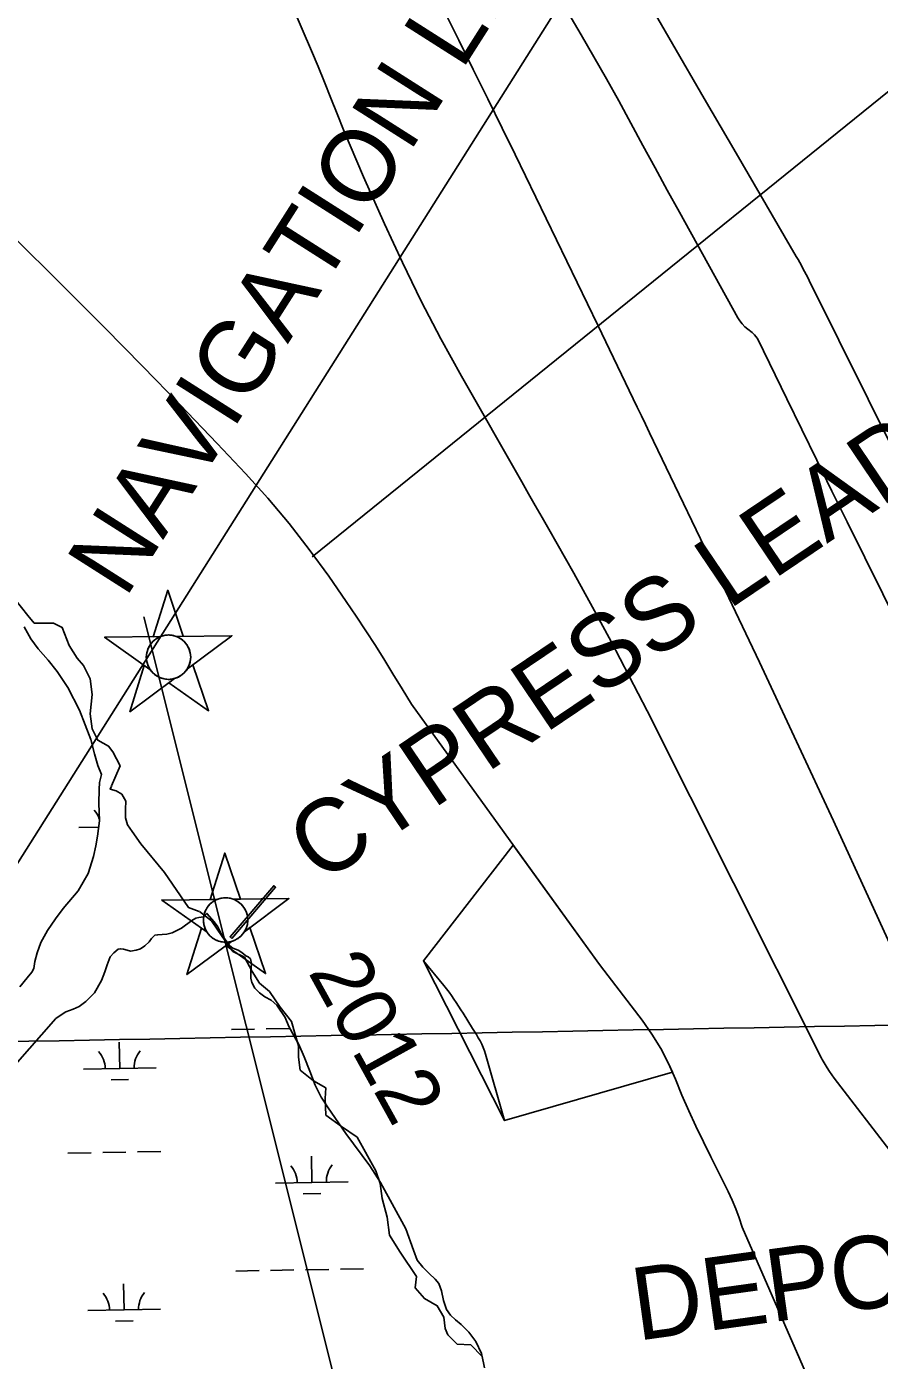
# Model space of a CAD drawing. Extents: x 3925854 to 3964121, y 224593 to 250589.
# Drawn here: x 3946796 to 3947969, y 235951 to 237787 of the extents above; entities that cross this region are included whole.
import ezdxf

# ---------------------------------------------------------------- set-up
doc = ezdxf.new("R2010")
doc.units = 0
for name, color, linetype in [('V-CHAN-DOCK', 7, 'Continuous'), ('V-CHAN-NAID', 7, 'Continuous'), ('V-GRID-MAJR', 7, 'Continuous'), ('V-RIVR-EDGE', 7, 'Continuous'), ('V-RIVR-IDEN', 7, 'Continuous'), ('V-RIVR-RANG', 7, 'Continuous'), ('V-TOPO-DPTH', 7, 'Continuous'), ('V-TOPO-MINR', 7, 'Continuous'), ('V-TOPO-SHOR', 7, 'Continuous'), ('V-UTIL-LINE', 7, 'Continuous'), ('V-WETL-SWMP', 7, 'Continuous')]:
    doc.layers.add(name, color=color, linetype=linetype)

msp = doc.modelspace()

# ---------------------------------------------------------------- linework, layer by layer
at = {"layer": 'V-CHAN-DOCK'}
msp.add_lwpolyline([(3947078.594, 236531.524), (3947138.764, 236602.031), (3947136.27, 236604.161), (3947076.098, 236533.654), (3947078.594, 236531.524)], dxfattribs=at)
at = {"layer": 'V-CHAN-NAID'}
for points in [[(3946980.066, 236947.098), (3946970.48, 236946.979), (3946990.365, 237010.862), (3947011.828, 236947.491), (3947002.241, 236947.373), (3947000.653, 236947.92), (3946998.547, 236948.499), (3946996.498, 236948.91), (3946994.457, 236949.178), (3946993.288, 236949.269), (3946991.752, 236949.321), (3946990.031, 236949.285), (3946988.662, 236949.188), (3946986.76, 236948.95), (3946985.399, 236948.705), (3946983.623, 236948.286), (3946982.101, 236947.836), (3946981.076, 236947.485)], [(3946980.066, 236947.098), (3946903.579, 236946.15), (3946966.017, 236901.958), (3946964.867, 236903.845), (3946964.025, 236905.457), (3946963.162, 236907.409), (3946962.426, 236909.449), (3946962.036, 236910.764), (3946961.643, 236912.383), (3946961.371, 236913.823), (3946961.152, 236915.417), (3946961.009, 236917.151), (3946960.966, 236918.731), (3946961.033, 236920.807), (3946961.184, 236922.428), (3946961.533, 236924.638), (3946961.977, 236926.57), (3946962.543, 236928.469), (3946963.165, 236930.16), (3946963.861, 236931.762), (3946964.645, 236933.313), (3946965.672, 236935.07), (3946966.674, 236936.56), (3946967.649, 236937.848), (3946968.629, 236939.013), (3946969.911, 236940.376), (3946970.943, 236941.361), (3946972.633, 236942.791), (3946973.828, 236943.684), (3946975.493, 236944.787), (3946977.206, 236945.766), (3946978.638, 236946.478)], [(3947002.241, 236947.373), (3947078.729, 236948.319), (3947017.405, 236902.594), (3947018.287, 236904.101), (3947019.229, 236905.967), (3947019.913, 236907.565), (3947020.614, 236909.534), (3947021.124, 236911.329), (3947021.49, 236912.976), (3947021.812, 236914.993), (3947021.967, 236916.569), (3947022.048, 236918.777), (3947021.978, 236920.838), (3947021.747, 236923.054), (3947021.446, 236924.806), (3947020.912, 236927.028), (3947020.23, 236929.155), (3947019.442, 236931.122), (3947018.766, 236932.553), (3947017.722, 236934.449), (3947016.626, 236936.15), (3947015.38, 236937.828), (3947014.089, 236939.342), (3947012.79, 236940.683), (3947011.129, 236942.183), (3947009.359, 236943.56), (3947007.653, 236944.704), (3947005.744, 236945.799), (3947004.258, 236946.532)], [(3946999.629, 236889.34), (3946938.305, 236843.615), (3946958.19, 236907.497), (3946966.017, 236901.958), (3946966.67, 236901.007), (3946968.089, 236899.175), (3946969.33, 236897.783), (3946970.825, 236896.309), (3946972.238, 236895.085), (3946973.714, 236893.958), (3946975.136, 236892.998), (3946976.834, 236891.995), (3946978.565, 236891.118), (3946980.372, 236890.342), (3946981.828, 236889.814), (3946983.466, 236889.317), (3946985.703, 236888.796), (3946987.24, 236888.539), (3946989.27, 236888.322), (3946990.809, 236888.248), (3946992.67, 236888.262), (3946994.357, 236888.373), (3946996.063, 236888.582), (3946997.959, 236888.93)], [(3947017.405, 236902.594), (3947025.091, 236908.326), (3947046.553, 236844.955), (3946991.942, 236883.609), (3946999.629, 236889.34), (3947001.285, 236889.848), (3947002.886, 236890.439), (3947005.026, 236891.395), (3947006.743, 236892.313), (3947008.587, 236893.463), (3947010.302, 236894.709), (3947011.83, 236895.984), (3947013.094, 236897.176), (3947014.45, 236898.623), (3947015.626, 236900.048), (3947016.717, 236901.542)], [(3947058.587, 236585.209), (3947049.001, 236585.09), (3947068.886, 236648.973), (3947090.349, 236585.602), (3947080.762, 236585.484), (3947079.174, 236586.031), (3947077.068, 236586.61), (3947075.019, 236587.021), (3947072.978, 236587.289), (3947071.809, 236587.38), (3947070.273, 236587.432), (3947068.552, 236587.396), (3947067.183, 236587.299), (3947065.281, 236587.061), (3947063.92, 236586.816), (3947062.144, 236586.397), (3947060.622, 236585.947), (3947059.597, 236585.596)], [(3947058.587, 236585.209), (3946982.1, 236584.261), (3947044.538, 236540.069), (3947043.388, 236541.956), (3947042.546, 236543.568), (3947041.683, 236545.52), (3947040.947, 236547.56), (3947040.557, 236548.875), (3947040.164, 236550.494), (3947039.892, 236551.934), (3947039.673, 236553.528), (3947039.53, 236555.262), (3947039.487, 236556.842), (3947039.554, 236558.918), (3947039.705, 236560.539), (3947040.054, 236562.749), (3947040.498, 236564.681), (3947041.064, 236566.58), (3947041.686, 236568.271), (3947042.382, 236569.873), (3947043.166, 236571.424), (3947044.193, 236573.181), (3947045.195, 236574.671), (3947046.17, 236575.959), (3947047.15, 236577.124), (3947048.432, 236578.487), (3947049.464, 236579.472), (3947051.154, 236580.902), (3947052.349, 236581.795), (3947054.014, 236582.898), (3947055.727, 236583.877), (3947057.159, 236584.589)], [(3947080.762, 236585.484), (3947157.25, 236586.43), (3947095.926, 236540.705), (3947096.808, 236542.212), (3947097.75, 236544.078), (3947098.434, 236545.676), (3947099.135, 236547.645), (3947099.645, 236549.44), (3947100.011, 236551.087), (3947100.333, 236553.104), (3947100.488, 236554.68), (3947100.569, 236556.888), (3947100.499, 236558.949), (3947100.268, 236561.165), (3947099.967, 236562.917), (3947099.433, 236565.139), (3947098.751, 236567.266), (3947097.963, 236569.233), (3947097.287, 236570.664), (3947096.243, 236572.56), (3947095.147, 236574.261), (3947093.901, 236575.939), (3947092.61, 236577.453), (3947091.311, 236578.794), (3947089.65, 236580.294), (3947087.88, 236581.671), (3947086.174, 236582.815), (3947084.265, 236583.91), (3947082.779, 236584.643)], [(3947078.15, 236527.451), (3947016.826, 236481.726), (3947036.711, 236545.608), (3947044.538, 236540.069), (3947045.191, 236539.118), (3947046.61, 236537.286), (3947047.851, 236535.894), (3947049.346, 236534.42), (3947050.759, 236533.196), (3947052.235, 236532.069), (3947053.657, 236531.109), (3947055.355, 236530.106), (3947057.086, 236529.229), (3947058.893, 236528.453), (3947060.349, 236527.925), (3947061.987, 236527.428), (3947064.224, 236526.907), (3947065.761, 236526.65), (3947067.791, 236526.433), (3947069.33, 236526.359), (3947071.191, 236526.373), (3947072.878, 236526.484), (3947074.584, 236526.693), (3947076.48, 236527.041)], [(3947095.926, 236540.705), (3947103.612, 236546.437), (3947125.074, 236483.066), (3947070.463, 236521.72), (3947078.15, 236527.451), (3947079.806, 236527.959), (3947081.407, 236528.55), (3947083.547, 236529.506), (3947085.264, 236530.424), (3947087.108, 236531.574), (3947088.823, 236532.82), (3947090.351, 236534.095), (3947091.615, 236535.287), (3947092.971, 236536.734), (3947094.147, 236538.159), (3947095.238, 236539.653)]]:
    msp.add_lwpolyline(points, close=True, dxfattribs=at)
for centre in [(3946991.506, 236918.781), (3947070.027, 236556.892)]:
    msp.add_circle(centre, 30.541, dxfattribs=at)
at = {"layer": 'V-GRID-MAJR'}
msp.add_spline([(3930006.603, 236087.686), (3935327.129, 236182.494), (3940647.643, 236278.076), (3945968.142, 236374.431), (3951288.627, 236471.56), (3956609.098, 236569.464), (3961929.554, 236668.141), (3961929.555, 236668.141)], degree=3, dxfattribs=at)
at = {"layer": 'V-RIVR-EDGE'}
for points in [[(3946780.342, 236997.96), (3946798.034, 236976.336), (3946806.88, 236965.524), (3946833.418, 236965.524), (3946845.213, 236959.627), (3946855.042, 236935.055), (3946865.854, 236917.362), (3946874.7, 236907.534), (3946883.546, 236888.858), (3946886.495, 236867.235), (3946883.546, 236840.697), (3946886.495, 236820.056), (3946894.358, 236804.329), (3946909.101, 236796.466), (3946914.999, 236788.603), (3946924.828, 236768.945), (3946913.033, 236741.424)], [(3946913.197, 236741.127), (3946911.283, 236736.98), (3946919.577, 236734.747), (3946927.233, 236729.962), (3946932.656, 236720.392), (3946932.337, 236709.546), (3946932.337, 236697.423), (3946934.889, 236687.853), (3946941.588, 236678.921), (3946953.391, 236661.695), (3946985.93, 236622.139), (3947018.787, 236573.969), (3947033.461, 236568.546)], [(3947033.929, 236568.434), (3947050.638, 236555.657), (3947065.382, 236534.033), (3947073.245, 236523.221), (3947080.125, 236513.392), (3947095.852, 236505.529), (3947106.663, 236485.871), (3947116.492, 236470.145), (3947130.253, 236458.35), (3947144.996, 236436.726), (3947160.723, 236417.068), (3947165.637, 236399.376), (3947170.552, 236383.65), (3947170.552, 236367.924), (3947172.517, 236350.232), (3947191.192, 236335.488), (3947207.902, 236325.659), (3947206.919, 236310.916), (3947207.902, 236288.309), (3947229.525, 236272.583), (3947251.149, 236257.839), (3947276.704, 236211.643), (3947282.602, 236193.951), (3947285.55, 236173.31), (3947292.431, 236147.755), (3947295.379, 236123.183), (3947310.123, 236099.593), (3947332.729, 236066.175), (3947330.764, 236050.448), (3947343.541, 236035.705), (3947361.233, 236025.876), (3947370.079, 236010.15), (3947372.045, 235994.423), (3947375.977, 235985.577), (3947388.755, 235972.8), (3947407.43, 235971.817), (3947423.156, 235956.09), (3947426.105, 235940.364)]]:
    msp.add_lwpolyline(points, dxfattribs=at)
at = {"layer": 'V-RIVR-RANG'}
msp.add_lwpolyline([(3946957.437, 236974.182), (3947380.075, 235285.015)], dxfattribs=at)
at = {"layer": 'V-TOPO-DPTH'}
msp.add_line((3947342.19, 236500.66), (3947453.89, 236280.69), dxfattribs=at)
for points in [[(3947403.666, 238040.429), (3947559.317, 237775.587), (3947576.826, 237745.398), (3947594.099, 237715.077), (3947611.02, 237684.558), (3947627.707, 237653.906), (3947644.275, 237623.188), (3947660.92, 237592.511), (3947677.68, 237561.897), (3947694.517, 237531.324), (3947774.824, 237386.155), (3947777.644, 237381.72), (3947780.785, 237377.559), (3947784.408, 237373.809), (3947788.351, 237370.334), (3947794.355, 237365.661), (3947797.736, 237362.677), (3947799.756, 237360.455), (3947801.441, 237357.994), (3947802.157, 237356.676), (3947842.097, 237274.575), (3947862.771, 237232.19), (3947883.504, 237189.833), (3947904.325, 237147.521), (3947925.205, 237105.237), (3948293.17, 236362.03)], [(3947988.605, 236233.372), (3947907.395, 236339.145), (3947904.009, 236343.741), (3947900.751, 236348.422), (3947897.681, 236353.23), (3947894.739, 236358.122), (3947890.826, 236364.932), (3947889.948, 236366.49), (3947889.089, 236368.057), (3947887.441, 236371.23), (3947649.862, 236845.126), (3947625.477, 236892.855), (3947600.611, 236940.328), (3947575.026, 236987.417), (3947548.96, 237034.25), (3947514.646, 237094.812), (3947505.37, 237111.167), (3947496.085, 237127.518), (3947486.787, 237143.861), (3947477.479, 237160.199), (3947394.556, 237305.613), (3947366.204, 237357.125), (3947338.91, 237409.171), (3947313.202, 237462.018), (3947288.551, 237515.4), (3947259.91, 237579.971), (3947250.516, 237601.528), (3947241.312, 237623.164), (3947232.39, 237644.919), (3947223.658, 237666.752), (3947214.974, 237688.607), (3947206.166, 237710.41), (3947197.171, 237732.138), (3947188.051, 237753.814), (3947161.353, 237816.515)], [(3947988.605, 236233.372), (3947907.395, 236339.145), (3947904.009, 236343.741), (3947900.751, 236348.422), (3947897.681, 236353.23), (3947894.739, 236358.122), (3947890.826, 236364.932), (3947889.948, 236366.49), (3947889.089, 236368.057), (3947887.441, 236371.23), (3947649.862, 236845.126), (3947625.477, 236892.855), (3947600.611, 236940.328), (3947575.026, 236987.417), (3947548.96, 237034.25), (3947514.646, 237094.812), (3947505.37, 237111.167), (3947496.085, 237127.518), (3947486.787, 237143.861), (3947477.479, 237160.199), (3947394.556, 237305.613), (3947366.204, 237357.125), (3947338.91, 237409.171), (3947313.202, 237462.018), (3947288.551, 237515.4), (3947259.91, 237579.971), (3947250.516, 237601.528), (3947241.312, 237623.164), (3947232.39, 237644.919), (3947223.658, 237666.752), (3947214.974, 237688.607), (3947206.166, 237710.41), (3947197.171, 237732.138), (3947188.051, 237753.814), (3947161.353, 237816.515)], [(3946688.902, 237586.154), (3946851.734, 237424.59), (3946904.003, 237372.225), (3946955.931, 237319.526), (3947007.347, 237266.328), (3947058.422, 237212.798), (3947097.489, 237171.455), (3947127.966, 237137.69), (3947157.368, 237103.055), (3947185.16, 237067.114), (3947211.878, 237030.303), (3947236.122, 236995.245), (3947249.749, 236975.203), (3947263.164, 236955.022), (3947276.26, 236934.633), (3947289.144, 236914.105), (3947300.337, 236895.955), (3947313.126, 236875.066), (3947325.822, 236854.122), (3947580.686, 236500.586), (3947585.905, 236494.019), (3947643.112, 236419.08), (3947656.559, 236399.848), (3947668.875, 236379.978), (3947679.492, 236359.151), (3947688.977, 236337.687), (3947697.891, 236315.865), (3947707.192, 236294.217), (3947717.076, 236272.828), (3947727.347, 236251.612), (3947737.792, 236230.76), (3947743.726, 236218.888), (3947749.646, 236207.009), (3947755.545, 236195.12), (3947761.431, 236183.224), (3947767.008, 236171.204), (3947772.191, 236159.028), (3947776.783, 236146.616), (3947780.98, 236134.048), (3948177.669, 235225.371)], [(3947684.725, 236347.309), (3947453.89, 236280.69), (3947427.726, 236372.119), (3947426.189, 236376.861), (3947424.438, 236381.514), (3947422.369, 236386.035), (3947420.087, 236390.466), (3947417.612, 236394.813), (3947415.097, 236399.134), (3947412.519, 236403.42), (3947409.901, 236407.681), (3947396.922, 236428.463), (3947393.801, 236433.412), (3947390.651, 236438.341), (3947387.457, 236443.242), (3947384.233, 236448.124), (3947380.913, 236452.937), (3947377.495, 236457.677), (3947373.929, 236462.306), (3947370.264, 236466.862), (3947342.19, 236500.66), (3947465.713, 236660.072)], [(3947465.713, 236660.072), (3947580.686, 236500.586), (3947585.905, 236494.019), (3947643.112, 236419.08), (3947656.559, 236399.848), (3947668.875, 236379.978), (3947679.492, 236359.151), (3947684.725, 236347.309)], [(3947453.89, 236280.69), (3947427.726, 236372.119), (3947426.189, 236376.861), (3947424.438, 236381.514), (3947422.369, 236386.035), (3947420.087, 236390.466), (3947417.612, 236394.813), (3947415.097, 236399.134), (3947412.519, 236403.42), (3947409.901, 236407.681), (3947396.922, 236428.463), (3947393.801, 236433.412), (3947390.651, 236438.341), (3947387.457, 236443.242), (3947384.233, 236448.124), (3947380.913, 236452.937), (3947377.495, 236457.677), (3947373.929, 236462.306), (3947370.264, 236466.862), (3947342.19, 236500.66)]]:
    msp.add_lwpolyline(points, dxfattribs=at)
at = {"layer": 'V-TOPO-MINR'}
for points in [[(3948293.17, 236362.03), (3947925.205, 237105.237), (3947904.325, 237147.521), (3947883.504, 237189.833), (3947862.771, 237232.19), (3947842.097, 237274.575), (3947802.157, 237356.676), (3947801.441, 237357.994), (3947799.756, 237360.455), (3947797.736, 237362.677), (3947794.355, 237365.661), (3947788.351, 237370.334), (3947784.408, 237373.809), (3947780.785, 237377.559), (3947777.644, 237381.72), (3947774.824, 237386.155), (3947694.517, 237531.324), (3947677.68, 237561.897), (3947660.92, 237592.511), (3947644.275, 237623.188), (3947627.707, 237653.906), (3947611.02, 237684.558), (3947594.099, 237715.077), (3947576.826, 237745.398), (3947559.317, 237775.587), (3947403.666, 238040.429)], [(3948319.902, 236537.459), (3947873.071, 237437.367), (3947870.955, 237441.58), (3947868.813, 237445.78), (3947866.633, 237449.96), (3947864.426, 237454.127), (3947862.179, 237458.271), (3947859.902, 237462.399), (3947857.58, 237466.502), (3947855.23, 237470.589), (3947772.35, 237612.929), (3947728.568, 237688.191), (3947684.829, 237763.478), (3947641.152, 237838.801)], [(3947988.605, 236233.372), (3947907.395, 236339.145), (3947904.009, 236343.741), (3947900.751, 236348.422), (3947897.681, 236353.23), (3947894.739, 236358.122), (3947890.826, 236364.932), (3947889.948, 236366.49), (3947889.089, 236368.057), (3947887.441, 236371.23), (3947649.862, 236845.126), (3947625.477, 236892.855), (3947600.611, 236940.328), (3947575.026, 236987.417), (3947548.96, 237034.25), (3947514.646, 237094.812), (3947505.37, 237111.167), (3947496.085, 237127.518), (3947486.787, 237143.861), (3947477.479, 237160.199), (3947394.556, 237305.613), (3947366.204, 237357.125), (3947338.91, 237409.171), (3947313.202, 237462.018), (3947288.551, 237515.4), (3947259.91, 237579.971), (3947250.516, 237601.528), (3947241.312, 237623.164), (3947232.39, 237644.919), (3947223.658, 237666.752), (3947214.974, 237688.607), (3947206.166, 237710.41), (3947197.171, 237732.138), (3947188.051, 237753.814), (3947161.353, 237816.515)], [(3948042.865, 236394.853), (3947956.573, 236584.258), (3947906.347, 236693.656), (3947855.697, 236802.856), (3947804.41, 236911.758), (3947752.699, 237020.462), (3947658.97, 237216.024), (3947653.356, 237227.733), (3947647.741, 237239.441), (3947642.123, 237251.148), (3947636.503, 237262.855), (3947582.23, 237375.885), (3947553.913, 237434.694), (3947525.511, 237493.463), (3947496.982, 237552.17), (3947468.369, 237610.836), (3947450.682, 237647), (3947430.804, 237687.532), (3947410.869, 237728.035), (3947390.846, 237768.494), (3947370.764, 237808.925)], [(3948177.669, 235225.371), (3947780.98, 236134.048), (3947776.783, 236146.616), (3947772.191, 236159.028), (3947767.008, 236171.204), (3947761.431, 236183.224), (3947755.545, 236195.12), (3947749.646, 236207.009), (3947743.726, 236218.888), (3947737.792, 236230.76), (3947727.347, 236251.612), (3947717.076, 236272.828), (3947707.192, 236294.217), (3947697.891, 236315.865), (3947688.977, 236337.687), (3947679.492, 236359.151), (3947668.875, 236379.978), (3947656.559, 236399.848), (3947643.112, 236419.08), (3947585.905, 236494.019), (3947580.686, 236500.586), (3947325.822, 236854.122), (3947313.126, 236875.066), (3947300.337, 236895.955), (3947289.144, 236914.105), (3947276.26, 236934.633), (3947263.164, 236955.022), (3947249.749, 236975.203), (3947236.122, 236995.245), (3947211.878, 237030.303), (3947185.16, 237067.114), (3947157.368, 237103.055), (3947127.966, 237137.69), (3947097.489, 237171.455), (3947058.422, 237212.798), (3947007.347, 237266.328), (3946955.931, 237319.526), (3946904.003, 237372.225), (3946851.734, 237424.59), (3946688.902, 237586.154)], [(3946957.437, 236974.182), (3947380.075, 235285.015)], [(3946957.437, 236974.182), (3947380.075, 235285.015)], [(3947453.89, 236280.69), (3947427.726, 236372.119), (3947426.189, 236376.861), (3947424.438, 236381.514), (3947422.369, 236386.035), (3947420.087, 236390.466), (3947417.612, 236394.813), (3947415.097, 236399.134), (3947412.519, 236403.42), (3947409.901, 236407.681), (3947396.922, 236428.463), (3947393.801, 236433.412), (3947390.651, 236438.341), (3947387.457, 236443.242), (3947384.233, 236448.124), (3947380.913, 236452.937), (3947377.495, 236457.677), (3947373.929, 236462.306), (3947370.264, 236466.862), (3947342.19, 236500.66)]]:
    msp.add_lwpolyline(points, dxfattribs=at)
at = {"layer": 'V-TOPO-SHOR'}
for points in [[(3946899.181, 236757.118), (3946896.76, 236746.128), (3946896.111, 236736.693), (3946895.513, 236717.982), (3946896.412, 236693.48), (3946893.86, 236672.523), (3946891.407, 236658.91), (3946888.241, 236644.433), (3946880.753, 236620.741), (3946867.318, 236596.954), (3946846.703, 236572.562), (3946835.845, 236558.361), (3946825.14, 236542.586), (3946815.824, 236526.091), (3946810.562, 236511.814), (3946807.777, 236499.606), (3946806.077, 236490.183), (3946803.558, 236484.969), (3946796.986, 236477.359), (3946787.025, 236464.897)], [(3946982.703, 236536.716), (3946989.183, 236537.33), (3946996.381, 236539.333), (3947009.407, 236545.459), (3947023.72, 236556.291), (3947029.186, 236559.541), (3947033.399, 236560.534), (3947039.531, 236561.329), (3947044.286, 236565.92)], [(3946780.729, 236357.467), (3946836.5, 236421.102), (3946841.27, 236424.537), (3946850.271, 236430.539), (3946860.286, 236433.906), (3946868.557, 236437.644), (3946877.921, 236444.517), (3946889.625, 236456.608), (3946899.3, 236473.797), (3946904.002, 236485.457), (3946907.281, 236495.207), (3946911.447, 236505.998), (3946916.071, 236511.71), (3946922.258, 236516.527), (3946925.242, 236517.36), (3946929.432, 236516.781), (3946934.837, 236515.31), (3946939.369, 236514.2), (3946947.082, 236515.323), (3946953.056, 236517.342), (3946959.057, 236521.286), (3946964.902, 236526.808), (3946968.113, 236531.487), (3946972.719, 236535.798), (3946976.753, 236536.622), (3946982.703, 236536.716)]]:
    msp.add_lwpolyline(points, dxfattribs=at)
at = {"layer": 'V-UTIL-LINE'}
msp.add_line((3947949.336, 238483.295), (3945978.591, 235358.555), dxfattribs=at)
msp.add_lwpolyline([(3947189.215, 237056.732), (3949959.323, 239295.941), (3952383.619, 242569.796)], dxfattribs=at)
at = {"layer": 'V-WETL-SWMP'}
for p, q in [((3946868.279, 236684.367), (3946895.363, 236684.859)), ((3947077.963, 236406.2), (3947109.958, 236406.781)), ((3947125.955, 236407.072), (3947157.95, 236407.654)), ((3946924.319, 236352.656), (3946923.664, 236388.65)), ((3946874.327, 236351.747), (3946974.311, 236353.565)), ((3946912.601, 236337.009), (3946936.597, 236337.445)), ((3946853.022, 236235.908), (3946885.016, 236236.49)), ((3946901.014, 236236.781), (3946933.008, 236237.362)), ((3946949.006, 236237.653), (3946981, 236238.235)), ((3947188.654, 236195.573), (3947188, 236231.567)), ((3947138.663, 236194.664), (3947238.646, 236196.482)), ((3947176.937, 236179.927), (3947200.933, 236180.363)), ((3947084.011, 236073.58), (3947116.006, 236074.161)), ((3947132.003, 236074.452), (3947163.998, 236075.034)), ((3947179.995, 236075.325), (3947211.99, 236075.907)), ((3947227.987, 236076.198), (3947259.982, 236076.779)), ((3946930.367, 236020.035), (3946929.712, 236056.03)), ((3946880.375, 236019.126), (3946980.359, 236020.944)), ((3946918.649, 236004.389), (3946942.646, 236004.825))]:
    msp.add_line(p, q, dxfattribs=at)
for points in [[(3946787.024, 236464.896), (3946796.985, 236477.359), (3946803.558, 236484.969), (3946806.077, 236490.183), (3946807.776, 236499.607), (3946810.562, 236511.815), (3946815.824, 236526.09), (3946825.139, 236542.585), (3946835.844, 236558.361), (3946846.703, 236572.562), (3946867.319, 236596.954), (3946880.754, 236620.741), (3946888.24, 236644.433), (3946891.406, 236658.91), (3946893.861, 236672.522), (3946896.413, 236693.48), (3946895.513, 236717.982), (3946896.111, 236736.692), (3946896.761, 236746.129), (3946899.181, 236757.118), (3946894.451, 236769.776), (3946889.763, 236785.581), (3946884.426, 236805.244), (3946868.873, 236846.034), (3946852.841, 236877.035), (3946838.441, 236899.267), (3946826.053, 236914.825), (3946812.265, 236930.401), (3946801.947, 236943.833), (3946793.075, 236960.744)], [(3946780.728, 236357.466), (3946836.501, 236421.102), (3946841.269, 236424.537), (3946850.27, 236430.54), (3946860.286, 236433.906), (3946868.557, 236437.645), (3946877.92, 236444.518), (3946889.626, 236456.608), (3946899.3, 236473.798), (3946904.003, 236485.456), (3946907.281, 236495.208), (3946911.447, 236505.999), (3946916.071, 236511.71), (3946922.258, 236516.526), (3946925.243, 236517.361), (3946929.433, 236516.781), (3946934.837, 236515.31), (3946939.37, 236514.2), (3946947.082, 236515.322), (3946953.056, 236517.342), (3946959.056, 236521.286), (3946964.902, 236526.807), (3946968.113, 236531.487), (3946972.718, 236535.799), (3946976.753, 236536.621), (3946982.702, 236536.717), (3946989.182, 236537.33), (3946996.381, 236539.334), (3947009.407, 236545.459), (3947023.72, 236556.29), (3947029.186, 236559.541), (3947033.398, 236560.535), (3947039.531, 236561.328), (3947044.287, 236565.92), (3947054.283, 236554.592), (3947059.24, 236547.449), (3947065.044, 236536.643), (3947071.909, 236526.677), (3947075.343, 236521.808), (3947080.19, 236517.97), (3947087.253, 236515.152), (3947092.46, 236512.102), (3947097.999, 236507.658), (3947100.935, 236506.355), (3947104.197, 236503.34), (3947105.809, 236496.797), (3947104.626, 236486.742), (3947104.846, 236476.943), (3947106.161, 236470.628), (3947110.262, 236463.226), (3947116.474, 236456.846), (3947124.096, 236451.148), (3947132.78, 236446.484), (3947140.388, 236439.736), (3947152.054, 236422.438), (3947157.138, 236410.126), (3947164.312, 236397.086), (3947170.806, 236385.454), (3947178.279, 236368.562), (3947185.714, 236348.871), (3947193.155, 236329.53), (3947201.332, 236312.978), (3947211.281, 236298.152), (3947235.653, 236262.843), (3947268.299, 236218.328), (3947283.389, 236195.387), (3947317.879, 236131.605), (3947328.688, 236102.423), (3947333.399, 236088.367), (3947341.32, 236078.815), (3947349.953, 236070.304), (3947358.596, 236062.493), (3947363.414, 236056.481), (3947367.128, 236046.286), (3947369.75, 236032.957), (3947373.785, 236020.658), (3947379.63, 236012.884), (3947386.192, 236006.499), (3947394.149, 235999.746), (3947404.859, 235989.458), (3947414.132, 235976.39), (3947421.959, 235959.843), (3947425.262, 235945.105)]]:
    msp.add_lwpolyline(points, dxfattribs=at)
for centre, start, end in [((3946863.028, 236684.746), 19.233856, 41.813537), ((3946869.076, 236352.126), 0.269879, 41.813537), ((3946979.544, 236354.135), 140.269876, 181.813534), ((3947133.412, 236195.044), 0.269879, 41.813537), ((3947243.88, 236197.052), 140.269876, 181.813534), ((3946875.125, 236019.506), 0.269879, 41.813537), ((3946985.592, 236021.515), 140.269876, 181.813534)]:
    msp.add_arc(centre, 35.246, start, end, dxfattribs=at)

# ---------------------------------------------------------------- texts
at = {"layer": 'V-CHAN-NAID'}
for s, rotation, p in [('NAVIGATION LIGHT (1.3)', 57.518436, (3946932.022, 236998.33)), ('CYPRESS LEADING', 34.00834, (3947201.046, 236604.927)), ('DEPOT POINT "14"', 7.892921, (3947636.537, 235977.446))]:
    msp.add_text(s, height=100, rotation=rotation, dxfattribs=at).set_placement(p)
at = {"layer": 'V-RIVR-IDEN'}
msp.add_text('2012', height=82.9998, rotation=298.914938, dxfattribs=at).set_placement((3947182.771, 236485.34))

doc.saveas('drawing.dxf')
